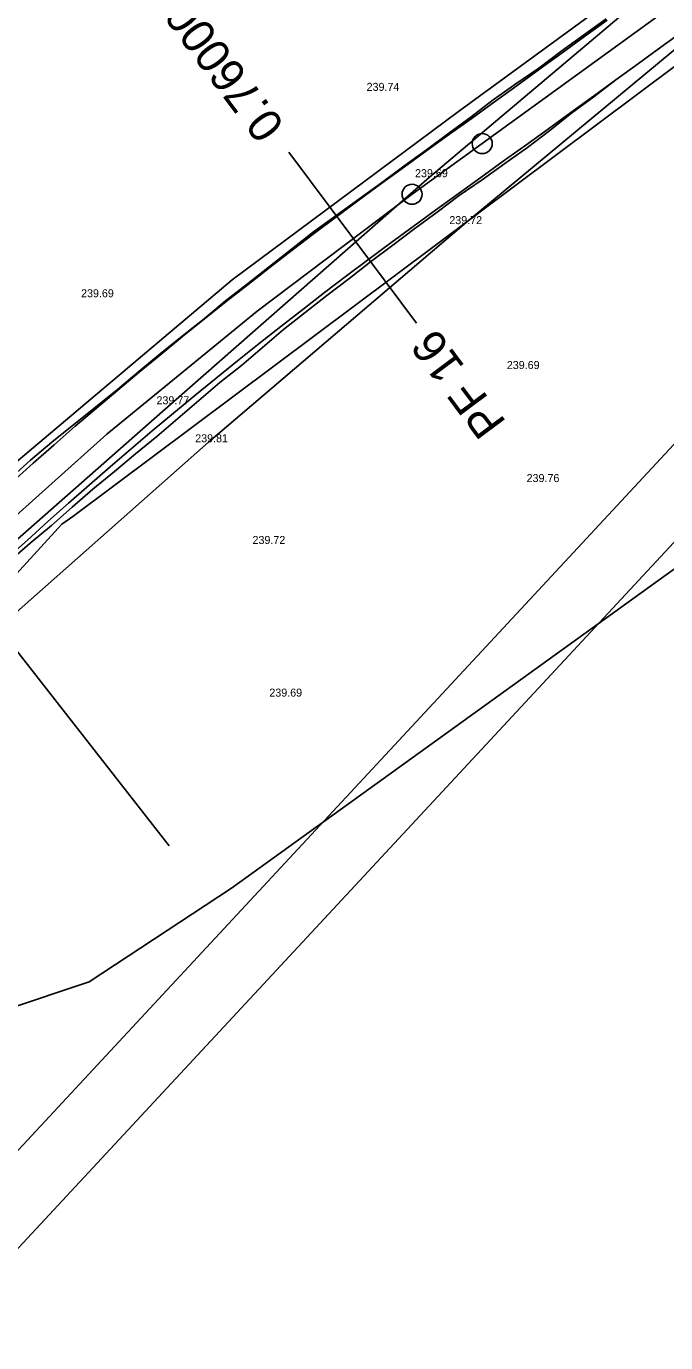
# Model space of a CAD drawing. Extents: x -555887 to -552101, y -1100251 to -1096546.
# Drawn here: x -555372.6 to -555324.6, y -1098751.9 to -1098653.3 of the extents above; entities that cross this region are included whole.
import ezdxf

# ---------------------------------------------------------------- set-up
doc = ezdxf.new("R2010")
doc.units = 0
for name, color, linetype in [('PARCELY_cesty', 7, 'Continuous'), ('POLYGONY_SITUACE_PF', 7, 'Continuous'), ('POLYGONY_SITUACE_PF_POPISY', 7, 'Continuous'), ('POLYGONY_SITUACE_PO', 7, 'Continuous'), ('ram_VC1', 7, 'Continuous'), ('vrstevnice', 7, 'Continuous'), ('Výškopis', 7, 'Continuous'), ('ZSST', 7, 'Continuous'), ('zájem', 7, 'Continuous')]:
    doc.layers.add(name, color=color, linetype=linetype)

msp = doc.modelspace()

# ---------------------------------------------------------------- linework, layer by layer
at = {"layer": 'PARCELY_cesty'}
msp.add_lwpolyline([(-555432.8, -1098748.4), (-555400.008, -1098712.208), (-555389.921, -1098701.565), (-555373.936, -1098686.469), (-555357.132, -1098672.276), (-555340.17, -1098659.659), (-555299.833, -1098630.198), (-555259.851, -1098600.294), (-555132.603, -1098503.989), (-555074.98, -1098461.38), (-555070.799, -1098455.669), (-555054.379, -1098443.798), (-555047.89, -1098441.68), (-555024.771, -1098425.173), (-554988.252, -1098399.708), (-554740.35, -1098228.23), (-554737.92, -1098224.21)], dxfattribs=at)
at = {"layer": 'POLYGONY_SITUACE_PF'}
for p, q in [((-555348.092, -1098669.13), (-555352.875, -1098662.717)), ((-555343.309, -1098675.542), (-555348.092, -1098669.13))]:
    msp.add_line(p, q, dxfattribs=at)
at = {"layer": 'POLYGONY_SITUACE_PO'}
for p, q in [((-555318.178, -1098647.4), (-555338.39, -1098662.074)), ((-555329.107, -1098652.728), (-555330.789, -1098653.955)), ((-555329.032, -1098652.831), (-555330.718, -1098654.053)), ((-555329.032, -1098652.831), (-555330.718, -1098654.053)), ((-555323.31, -1098653.616), (-555324.996, -1098654.842)), ((-555323.31, -1098653.616), (-555324.996, -1098654.842)), ((-555323.31, -1098653.616), (-555324.996, -1098654.842)), ((-555330.789, -1098653.955), (-555332.486, -1098655.162)), ((-555330.718, -1098654.053), (-555332.403, -1098655.276)), ((-555330.718, -1098654.053), (-555332.403, -1098655.276)), ((-555332.486, -1098655.162), (-555334.144, -1098656.423)), ((-555332.403, -1098655.276), (-555334.09, -1098656.498)), ((-555332.403, -1098655.276), (-555334.09, -1098656.498)), ((-555324.996, -1098654.842), (-555326.681, -1098656.067)), ((-555324.996, -1098654.842), (-555326.681, -1098656.067)), ((-555324.996, -1098654.842), (-555326.681, -1098656.067)), ((-555334.144, -1098656.423), (-555335.869, -1098657.591)), ((-555334.09, -1098656.498), (-555335.776, -1098657.719)), ((-555334.09, -1098656.498), (-555335.776, -1098657.719)), ((-555326.681, -1098656.067), (-555328.369, -1098657.291)), ((-555326.681, -1098656.067), (-555328.369, -1098657.291)), ((-555326.681, -1098656.067), (-555328.369, -1098657.291)), ((-555335.869, -1098657.591), (-555337.563, -1098658.801)), ((-555328.369, -1098657.291), (-555330.056, -1098658.515)), ((-555328.369, -1098657.291), (-555330.056, -1098658.515)), ((-555328.369, -1098657.291), (-555330.026, -1098658.557)), ((-555328.369, -1098657.291), (-555328.369, -1098657.291)), ((-555335.776, -1098657.719), (-555337.464, -1098658.939)), ((-555335.776, -1098657.719), (-555337.464, -1098658.939)), ((-555330.056, -1098658.515), (-555331.744, -1098659.738)), ((-555330.056, -1098658.515), (-555331.744, -1098659.738)), ((-555330.026, -1098658.557), (-555331.699, -1098659.799)), ((-555337.563, -1098658.801), (-555339.224, -1098660.058)), ((-555337.464, -1098658.939), (-555339.152, -1098660.158)), ((-555337.464, -1098658.939), (-555339.152, -1098660.158)), ((-555339.224, -1098660.058), (-555340.897, -1098661.3)), ((-555339.152, -1098660.158), (-555340.841, -1098661.377)), ((-555339.152, -1098660.158), (-555340.841, -1098661.377)), ((-555331.744, -1098659.738), (-555333.432, -1098660.96)), ((-555331.744, -1098659.738), (-555333.432, -1098660.96)), ((-555331.699, -1098659.799), (-555333.329, -1098661.102)), ((-555340.897, -1098661.3), (-555342.576, -1098662.533)), ((-555340.841, -1098661.377), (-555342.531, -1098662.596)), ((-555340.841, -1098661.377), (-555342.531, -1098662.596)), ((-555333.432, -1098660.96), (-555335.121, -1098662.181)), ((-555333.432, -1098660.96), (-555335.121, -1098662.181)), ((-555333.329, -1098661.102), (-555334.992, -1098662.359)), ((-555342.576, -1098662.533), (-555344.261, -1098663.759)), ((-555342.531, -1098662.596), (-555344.22, -1098663.816)), ((-555342.531, -1098662.596), (-555344.22, -1098663.816)), ((-555338.39, -1098662.074), (-555343.649, -1098665.87)), ((-555335.121, -1098662.181), (-555336.811, -1098663.401)), ((-555335.121, -1098662.181), (-555336.811, -1098663.401)), ((-555334.992, -1098662.359), (-555336.692, -1098663.566)), ((-555336.811, -1098663.401), (-555338.5, -1098664.621)), ((-555336.811, -1098663.401), (-555338.5, -1098664.621)), ((-555336.692, -1098663.566), (-555338.388, -1098664.777)), ((-555344.261, -1098663.759), (-555345.941, -1098665.005)), ((-555344.22, -1098663.816), (-555345.913, -1098665.042)), ((-555344.22, -1098663.816), (-555345.913, -1098665.042)), ((-555345.941, -1098665.005), (-555347.642, -1098666.228)), ((-555345.913, -1098665.042), (-555347.605, -1098666.279)), ((-555345.913, -1098665.042), (-555347.605, -1098666.279)), ((-555338.5, -1098664.621), (-555340.19, -1098665.84)), ((-555338.5, -1098664.621), (-555340.19, -1098665.84)), ((-555338.388, -1098664.777), (-555340.108, -1098665.953)), ((-555343.649, -1098665.87), (-555355.267, -1098674.628)), ((-555347.642, -1098666.228), (-555349.336, -1098667.462)), ((-555347.605, -1098666.279), (-555349.288, -1098667.527)), ((-555347.605, -1098666.279), (-555349.288, -1098667.527)), ((-555340.19, -1098665.84), (-555341.879, -1098667.059)), ((-555340.19, -1098665.84), (-555341.879, -1098667.059)), ((-555340.108, -1098665.953), (-555341.771, -1098667.209)), ((-555349.336, -1098667.462), (-555351.033, -1098668.692)), ((-555349.288, -1098667.527), (-555350.96, -1098668.79)), ((-555349.288, -1098667.527), (-555350.96, -1098668.79)), ((-555341.879, -1098667.059), (-555343.56, -1098668.276)), ((-555341.879, -1098667.059), (-555343.56, -1098668.276)), ((-555341.771, -1098667.209), (-555343.438, -1098668.445)), ((-555343.56, -1098668.276), (-555345.232, -1098669.499)), ((-555343.56, -1098668.276), (-555345.232, -1098669.499)), ((-555343.438, -1098668.445), (-555345.101, -1098669.677)), ((-555351.033, -1098668.692), (-555352.685, -1098669.982)), ((-555350.96, -1098668.79), (-555352.631, -1098670.053)), ((-555350.96, -1098668.79), (-555352.631, -1098670.053)), ((-555345.232, -1098669.499), (-555346.896, -1098670.733)), ((-555345.232, -1098669.499), (-555346.896, -1098670.733)), ((-555352.685, -1098669.982), (-555354.324, -1098671.288)), ((-555352.631, -1098670.053), (-555354.291, -1098671.332)), ((-555352.631, -1098670.053), (-555354.291, -1098671.332)), ((-555345.101, -1098669.677), (-555346.751, -1098670.927)), ((-555354.324, -1098671.288), (-555355.975, -1098672.579)), ((-555354.291, -1098671.332), (-555355.941, -1098672.622)), ((-555354.291, -1098671.332), (-555355.941, -1098672.622)), ((-555346.896, -1098670.733), (-555348.549, -1098671.982)), ((-555346.896, -1098670.733), (-555348.549, -1098671.982)), ((-555346.751, -1098670.927), (-555348.385, -1098672.199)), ((-555348.549, -1098671.982), (-555350.202, -1098673.23)), ((-555348.549, -1098671.982), (-555350.202, -1098673.23)), ((-555348.385, -1098672.199), (-555350.024, -1098673.463)), ((-555355.975, -1098672.579), (-555357.636, -1098673.857)), ((-555355.941, -1098672.622), (-555357.589, -1098673.917)), ((-555355.941, -1098672.622), (-555357.589, -1098673.917)), ((-555350.202, -1098673.23), (-555351.842, -1098674.495)), ((-555350.202, -1098673.23), (-555351.842, -1098674.495)), ((-555357.636, -1098673.857), (-555359.234, -1098675.214)), ((-555357.589, -1098673.917), (-555359.224, -1098675.227)), ((-555357.589, -1098673.917), (-555359.224, -1098675.227)), ((-555350.024, -1098673.463), (-555351.664, -1098674.725)), ((-555355.267, -1098674.628), (-555366.511, -1098683.861)), ((-555359.234, -1098675.214), (-555360.882, -1098676.509)), ((-555359.224, -1098675.227), (-555360.859, -1098676.537)), ((-555359.224, -1098675.227), (-555360.859, -1098676.537)), ((-555351.842, -1098674.495), (-555353.474, -1098675.771)), ((-555351.842, -1098674.495), (-555353.474, -1098675.771)), ((-555351.664, -1098674.725), (-555353.281, -1098676.017)), ((-555353.474, -1098675.771), (-555355.103, -1098677.05)), ((-555353.474, -1098675.771), (-555355.103, -1098677.05)), ((-555353.281, -1098676.017), (-555354.857, -1098677.361)), ((-555360.882, -1098676.509), (-555362.514, -1098677.823)), ((-555360.859, -1098676.537), (-555362.477, -1098677.868)), ((-555360.859, -1098676.537), (-555362.477, -1098677.868)), ((-555355.103, -1098677.05), (-555356.72, -1098678.345)), ((-555355.103, -1098677.05), (-555356.72, -1098678.345)), ((-555354.857, -1098677.361), (-555356.435, -1098678.699)), ((-555362.514, -1098677.823), (-555364.127, -1098679.162)), ((-555362.477, -1098677.868), (-555364.09, -1098679.205)), ((-555362.477, -1098677.868), (-555364.09, -1098679.205)), ((-555356.72, -1098678.345), (-555358.336, -1098679.641)), ((-555356.72, -1098678.345), (-555358.336, -1098679.641)), ((-555364.127, -1098679.162), (-555365.736, -1098680.504)), ((-555364.09, -1098679.205), (-555365.697, -1098680.55)), ((-555364.09, -1098679.205), (-555365.697, -1098680.55)), ((-555356.435, -1098678.699), (-555358.066, -1098679.973)), ((-555358.336, -1098679.641), (-555359.935, -1098680.957)), ((-555358.336, -1098679.641), (-555359.935, -1098680.957)), ((-555358.066, -1098679.973), (-555359.635, -1098681.322)), ((-555365.736, -1098680.504), (-555367.371, -1098681.816)), ((-555365.697, -1098680.55), (-555367.294, -1098681.906)), ((-555365.697, -1098680.55), (-555367.294, -1098681.906)), ((-555359.935, -1098680.957), (-555361.53, -1098682.279)), ((-555359.935, -1098680.957), (-555361.53, -1098682.279)), ((-555359.635, -1098681.322), (-555361.199, -1098682.677)), ((-555367.371, -1098681.816), (-555369.002, -1098683.135)), ((-555367.294, -1098681.906), (-555368.891, -1098683.263)), ((-555367.294, -1098681.906), (-555368.891, -1098683.263)), ((-555361.53, -1098682.279), (-555363.119, -1098683.608)), ((-555361.53, -1098682.279), (-555363.119, -1098683.608)), ((-555369.002, -1098683.135), (-555370.643, -1098684.442)), ((-555368.891, -1098683.263), (-555370.465, -1098684.645)), ((-555368.891, -1098683.263), (-555370.465, -1098684.645)), ((-555361.199, -1098682.677), (-555362.774, -1098684.017)), ((-555366.511, -1098683.861), (-555377.362, -1098693.554)), ((-555363.119, -1098683.608), (-555364.698, -1098684.949)), ((-555363.119, -1098683.608), (-555364.698, -1098684.949)), ((-555362.774, -1098684.017), (-555364.372, -1098685.33)), ((-555370.643, -1098684.442), (-555372.241, -1098685.8)), ((-555370.465, -1098684.645), (-555372.04, -1098686.028)), ((-555370.465, -1098684.645), (-555372.04, -1098686.028)), ((-555364.698, -1098684.949), (-555366.277, -1098686.29)), ((-555364.698, -1098684.949), (-555366.277, -1098686.29)), ((-555372.241, -1098685.8), (-555373.797, -1098687.206)), ((-555372.04, -1098686.028), (-555373.604, -1098687.421)), ((-555372.04, -1098686.028), (-555373.604, -1098687.421)), ((-555364.372, -1098685.33), (-555365.96, -1098686.657)), ((-555366.277, -1098686.29), (-555367.833, -1098687.657)), ((-555366.277, -1098686.29), (-555367.833, -1098687.657)), ((-555365.96, -1098686.657), (-555367.561, -1098687.968)), ((-555367.833, -1098687.657), (-555369.39, -1098689.024)), ((-555367.833, -1098687.657), (-555369.39, -1098689.024)), ((-555367.561, -1098687.968), (-555369.119, -1098689.33)), ((-555369.39, -1098689.024), (-555370.936, -1098690.402)), ((-555369.39, -1098689.024), (-555370.936, -1098690.402)), ((-555369.119, -1098689.33), (-555370.665, -1098690.704)), ((-555370.936, -1098690.402), (-555372.476, -1098691.787)), ((-555370.936, -1098690.402), (-555372.476, -1098691.787)), ((-555370.665, -1098690.704), (-555372.261, -1098692.025)), ((-555372.476, -1098691.787), (-555374.011, -1098693.177)), ((-555372.476, -1098691.787), (-555374.011, -1098693.177)), ((-555372.261, -1098692.025), (-555373.826, -1098693.38))]:
    msp.add_line(p, q, dxfattribs=at)
for centre in [(-555338.39, -1098662.074), (-555343.649, -1098665.87)]:
    msp.add_circle(centre, 0.75, dxfattribs=at)
at = {"layer": 'ram_VC1'}
for points in [[(-554540.883, -1097849.107), (-554911.618, -1097504.634), (-555880.616, -1098547.506), (-555509.881, -1098891.979)], [(-554547.95, -1097849.366), (-554911.358, -1097511.7), (-555873.55, -1098547.246), (-555510.141, -1098884.912)]]:
    msp.add_lwpolyline(points, close=True, dxfattribs=at)
for points in [[(-554540.883, -1097849.107), (-554911.618, -1097504.634), (-555880.616, -1098547.506), (-555509.881, -1098891.979), (-554540.883, -1097849.107)], [(-555510.141, -1098884.912), (-555873.55, -1098547.246), (-554911.358, -1097511.7), (-554547.95, -1097849.366), (-555510.141, -1098884.912)]]:
    msp.add_lwpolyline(points, dxfattribs=at)
at = {"layer": 'vrstevnice'}
msp.add_lwpolyline([(-555306.349, -1098681.23), (-555357.179, -1098717.88), (-555367.859, -1098724.9), (-555380.489, -1098729.11), (-555384.139, -1098729.53), (-555393.129, -1098727.71), (-555396.499, -1098726.02), (-555402.119, -1098719.98), (-555404.499, -1098714.93), (-555405.909, -1098704.82), (-555405.489, -1098694.85), (-555402.119, -1098681.51), (-555398.049, -1098672.52), (-555392.989, -1098664.94), (-555377.829, -1098647.25), (-555362.519, -1098631.24), (-555353.669, -1098619.73), (-555346.649, -1098606.59), (-555345.389, -1098601.19)], dxfattribs=at)
at = {"layer": 'ZSST'}
msp.add_line((-555374.63, -1098698.36), (-555361.85, -1098714.7), dxfattribs=at)
for points in [[(-555047.93, -1098442.03), (-555072.12, -1098458.86), (-555088.34, -1098470.57), (-555126.84, -1098498.87), (-555144.37, -1098512.2), (-555194.54, -1098551.36), (-555231.55, -1098580.01), (-555250.25, -1098594.37), (-555270.85, -1098609.63), (-555289.58, -1098622.71), (-555305.43, -1098634.04), (-555318.12, -1098644.14), (-555342.33, -1098664.59), (-555361.73, -1098681.61), (-555377.43, -1098695.41), (-555388.84, -1098705.7), (-555402.21, -1098718.08), (-555414.99, -1098731.34), (-555426.44, -1098743.28)], [(-555374.63, -1098698.36), (-555358.9, -1098684.46), (-555339.75, -1098668.11), (-555314.71, -1098647.33), (-555303.03, -1098637.47), (-555287.5, -1098626.12)]]:
    msp.add_lwpolyline(points, dxfattribs=at)
at = {"layer": 'zájem'}
for points in [[(-555456.8, -1098789.9), (-555379.7, -1098701.24), (-555376.22, -1098697.48), (-555369.9, -1098690.59), (-555369.08, -1098690.01), (-555302.67, -1098640.32), (-555268.63, -1098614.85), (-555156.39, -1098530.87), (-555094.92, -1098484.89), (-555072.69, -1098467.65), (-555057.79, -1098455.7), (-554947.91, -1098379.76)], [(-554947.91, -1098379.76), (-555057.79, -1098455.7), (-555072.69, -1098467.65), (-555094.92, -1098484.89), (-555156.39, -1098530.87), (-555268.63, -1098614.85), (-555302.67, -1098640.32), (-555369.08, -1098690.01), (-555369.9, -1098690.59), (-555376.22, -1098697.48), (-555379.7, -1098701.24), (-555456.8, -1098789.9)]]:
    msp.add_lwpolyline(points, dxfattribs=at)

# ---------------------------------------------------------------- texts
at = {"layer": 'POLYGONY_SITUACE_PF_POPISY'}
for s, p in [('0.76000 km', (-555353.122, -1098660.714)), ('PF 16', (-555336.528, -1098682.96))]:
    msp.add_text(s, height=2.5, rotation=126.72075, dxfattribs=at).set_placement(p)
at = {"layer": 'Výškopis'}
for s, p in [('239.74', (-555347.053, -1098658.12)), ('239.69', (-555343.424, -1098664.59)), ('239.72', (-555340.854, -1098668.11)), ('239.69', (-555368.454, -1098673.59)), ('239.69', (-555336.544, -1098678.97)), ('239.77', (-555362.801, -1098681.61)), ('239.81', (-555359.9, -1098684.46)), ('239.76', (-555335.063, -1098687.44)), ('239.72', (-555355.604, -1098692.08)), ('239.69', (-555354.344, -1098703.52))]:
    msp.add_text(s, height=0.6, dxfattribs=at).set_placement(p)

doc.saveas('drawing.dxf')
